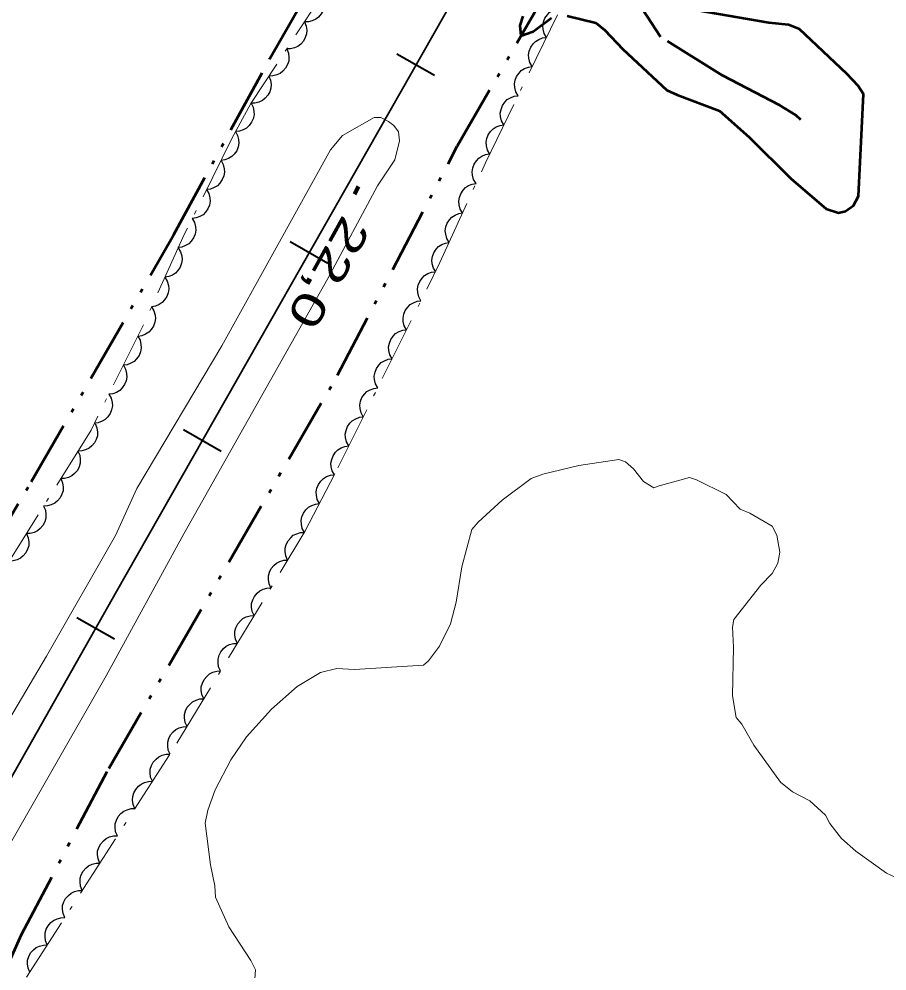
# Model space of a CAD drawing. Extents: x 386081 to 389416, y 5130568 to 5134082.
# Drawn here: x 387558.3 to 387638.7, y 5131484.2 to 5131572.3 of the extents above; entities that cross this region are included whole.
import ezdxf

# ---------------------------------------------------------------- set-up
doc = ezdxf.new("R2010")
doc.units = 0
doc.header["$LTSCALE"] = 1.2
for name, pattern in [('DASH_DOUBLE_DOT', [9.2, 5, -1.2, 0.3, -1.2, 0.3, -1.2]), ('DOT_DASHED', [7.7, 5, -1.2, 0.3, -1.2]), ('LONG_DASHED', [7.5, 6, -1.5])]:
    doc.linetypes.add(name, pattern=pattern)
for name, color, linetype, lineweight in [('1', 7, 'Continuous', 53), ('2', 7, 'Continuous', 13), ('23', 7, 'Continuous', 40), ('3', 7, 'Continuous', 140), ('4', 7, 'DASH_DOUBLE_DOT', 53), ('44', 7, 'Continuous', 25)]:
    doc.layers.add(name, color=color, linetype=linetype, lineweight=lineweight)

msp = doc.modelspace()

# ---------------------------------------------------------------- linework, layer by layer
at = {"layer": '1'}
for points in [[(387604.96, 5131572.54), (387604.69, 5131571.68), (387604.76, 5131570.72), (387605.92, 5131571.13), (387607.6, 5131572.4)], [(387609.06, 5131572.59), (387611.71, 5131571.93), (387612.56, 5131571.24), (387614.23, 5131569.49), (387618.3, 5131565.7), (387619.23, 5131565.26), (387623.17, 5131563.79), (387625.91, 5131561.34), (387629.75, 5131557.51), (387633.03, 5131554.73), (387634.17, 5131554.34), (387634.83, 5131554.5), (387635.57, 5131555.03), (387636.04, 5131555.9), (387636.48, 5131565.32), (387636.01, 5131566.09), (387634.95, 5131567.21), (387630.57, 5131571.36), (387629.56, 5131571.74), (387627.73, 5131571.94), (387621.08, 5131573.07)]]:
    msp.add_lwpolyline(points, dxfattribs=at)
at = {"layer": '2'}
for points in [[(387540.55, 5131478.3), (387543.89, 5131484.44), (387548.58, 5131492.52), (387560.89, 5131513.31), (387567.26, 5131524.47), (387569.25, 5131528.82), (387577.11, 5131542.04), (387587.16, 5131560.17), (387588.27, 5131561.49), (387591.21, 5131563.16), (387591.81, 5131563.16), (387592.54, 5131562.79), (387593.02, 5131562.42), (387593.44, 5131561.86), (387593.55, 5131561.01), (387593.11, 5131559.25), (387591.5, 5131556.84), (387586.91, 5131548.26), (387573.58, 5131524.65), (387566.39, 5131511.49), (387554.33, 5131490.45), (387547.71, 5131478.33)], [(387625.07, 5131526.92), (387625.97, 5131526.54), (387628.03, 5131525.36), (387628.48, 5131524.51), (387628.75, 5131522.95), (387628.55, 5131521.92), (387628.05, 5131520.96), (387626.98, 5131519.88), (387624.5, 5131516.71), (387624.37, 5131516), (387624.47, 5131514.15), (387624.36, 5131509.63), (387624.7, 5131507.62), (387625.22, 5131507.03), (387626.35, 5131505.09), (387628.82, 5131501.66), (387629.92, 5131500.76), (387631.51, 5131499.92), (387632.98, 5131498.58), (387633.36, 5131497.82), (387634.46, 5131496.44), (387635.79, 5131495.25), (387638.61, 5131493.23), (387640.62, 5131492.3)]]:
    msp.add_lwpolyline(points, dxfattribs=at)
at = {"layer": '2', "linetype": 'LONG_DASHED'}
for points in [[(387595.77, 5131512.49), (387596.24, 5131512.88), (387597.24, 5131514.25), (387598.26, 5131516.32), (387598.79, 5131518.3), (387599.33, 5131521.57), (387600.23, 5131525.03), (387600.83, 5131525.72), (387603.04, 5131527.76), (387605.74, 5131529.75), (387606.82, 5131530.15), (387610.15, 5131530.96), (387613.85, 5131531.53), (387614.46, 5131531.29), (387615.21, 5131530.65), (387616.13, 5131529.47), (387617.09, 5131528.88), (387617.57, 5131529.09), (387620.4, 5131529.86), (387621.04, 5131529.63), (387623.78, 5131528.29), (387625.07, 5131526.92)], [(387579.94, 5131480.88), (387580.22, 5131484.29), (387579.78, 5131485.13), (387577.76, 5131488.26), (387576.51, 5131491.01), (387576.47, 5131492.05), (387576.05, 5131494.01), (387575.56, 5131497.84), (387575.8, 5131499.05), (387576.49, 5131500.95), (387577.93, 5131503.71), (387579.4, 5131505.84), (387581.71, 5131508.41), (387584.09, 5131510.51), (387586.25, 5131511.79), (387587.76, 5131512.16), (387589.38, 5131512.09), (387595.77, 5131512.49)]]:
    msp.add_lwpolyline(points, dxfattribs=at)
at = {"layer": '23'}
for p, q in [((387593.31, 5131569.07), (387596.79, 5131567.09)), ((387583.44, 5131551.68), (387586.91, 5131549.7)), ((387573.56, 5131534.29), (387577.04, 5131532.3)), ((387563.69, 5131516.88), (387567.17, 5131514.92))]:
    msp.add_line(p, q, dxfattribs=at)
at = {"layer": '23', "lineweight": 35}
msp.add_lwpolyline([(388350.66, 5132898.63), (388202.91, 5132638.38), (388174.85, 5132589.18), (388148.16, 5132542.09), (388122.46, 5132497.01), (388036.96, 5132346.4), (388027.91, 5132330.61), (387994.29, 5132271.3), (387943.96, 5132182.8), (387915.65, 5132132.74), (387888.36, 5132084.71), (387863.09, 5132039.98), (387797.42, 5131924.62), (387647.54, 5131660.34), (387567.35, 5131519.3), (387534.84, 5131461.86), (387476.24, 5131358.73)], dxfattribs=at)
at = {"layer": '3'}
msp.add_line((387589.76, 5131556.79), (387589.37, 5131556.09), dxfattribs=at)
at = {"layer": '4'}
for points in [[(387542.58, 5131491.37), (387538.76, 5131492.88), (387540.3, 5131495.55), (387549.6, 5131512.73), (387559.47, 5131529.44), (387572.66, 5131552.34), (387581.55, 5131568.63), (387589.33, 5131582.17), (387594.48, 5131592.2), (387598.48, 5131601.01), (387601.21, 5131603.88)], [(387630.68, 5131562.95), (387630.24, 5131563.38), (387628.7, 5131564.3), (387623.43, 5131567.05), (387617.7, 5131570.63), (387613.12, 5131577.72), (387610.37, 5131581.22)], [(387566.42, 5131303.9), (387530.96, 5131346.09), (387515.69, 5131364.76), (387501.67, 5131380.58), (387499.1, 5131383.05), (387500.67, 5131386.61), (387516.18, 5131411.59), (387529.43, 5131434.73), (387541.53, 5131455.63), (387550.92, 5131473.93), (387557.21, 5131484.48), (387558.57, 5131487.55), (387566.63, 5131502.92), (387587.82, 5131539.32), (387598.88, 5131560.51), (387607.65, 5131575.65), (387611.01, 5131580.38)]]:
    msp.add_lwpolyline(points, dxfattribs=at)
at = {"layer": '44', "linetype": 'DOT_DASHED', "lineweight": 13}
for points in [[(387559.03, 5131483.59), (387572.94, 5131505.25), (387584.8, 5131524.86), (387587.84, 5131530.74), (387597.29, 5131549.74), (387601.5, 5131558.98), (387608.41, 5131573.21), (387610.77, 5131577.13), (387616.62, 5131586.21), (387623.15, 5131596.99), (387625.99, 5131602.26), (387629.7, 5131608.49), (387640.15, 5131626.74)], [(387602.48, 5131599.01), (387579.79, 5131564.47), (387578.03, 5131561.22), (387573.66, 5131552.4), (387569.76, 5131543.8), (387565, 5131534.24), (387545.23, 5131502.58), (387543.56, 5131500.59), (387539.99, 5131495.88), (387539.05, 5131493.88), (387538.04, 5131490.97), (387535.31, 5131484.12)]]:
    msp.add_lwpolyline(points, dxfattribs=at)
at = {"layer": '44'}
for points in [[(387586.4, 5131574.53), (387586.56, 5131574.15), (387586.6, 5131573.74), (387586.59, 5131573.41), (387586.48, 5131573.08), (387586.3, 5131572.76), (387586.04, 5131572.47), (387585.8, 5131572.26), (387585.47, 5131572.12), (387585.11, 5131572.03), (387584.75, 5131572.03)], [(387607.14, 5131570.59), (387606.93, 5131570.95), (387606.84, 5131571.35), (387606.8, 5131571.67), (387606.87, 5131572.02), (387607, 5131572.36), (387607.23, 5131572.68), (387607.44, 5131572.92), (387607.75, 5131573.1), (387608.09, 5131573.24), (387608.45, 5131573.29)], [(387584.75, 5131572.03), (387584.91, 5131571.64), (387584.96, 5131571.24), (387584.94, 5131570.91), (387584.83, 5131570.57), (387584.66, 5131570.25), (387584.4, 5131569.97), (387584.15, 5131569.75), (387583.83, 5131569.61), (387583.47, 5131569.52), (387583.11, 5131569.52)], [(387605.83, 5131567.89), (387605.62, 5131568.25), (387605.53, 5131568.65), (387605.49, 5131568.98), (387605.56, 5131569.32), (387605.69, 5131569.67), (387605.92, 5131569.98), (387606.13, 5131570.22), (387606.44, 5131570.4), (387606.78, 5131570.54), (387607.14, 5131570.59)], [(387583.11, 5131569.52), (387583.27, 5131569.13), (387583.31, 5131568.73), (387583.3, 5131568.4), (387583.19, 5131568.07), (387583.01, 5131567.74), (387582.75, 5131567.46), (387582.5, 5131567.25), (387582.18, 5131567.11), (387581.82, 5131567.02), (387581.46, 5131567.01)], [(387604.52, 5131565.19), (387604.31, 5131565.55), (387604.21, 5131565.95), (387604.18, 5131566.28), (387604.25, 5131566.62), (387604.38, 5131566.97), (387604.61, 5131567.28), (387604.82, 5131567.52), (387605.12, 5131567.7), (387605.47, 5131567.84), (387605.83, 5131567.89)], [(387581.46, 5131567.01), (387581.62, 5131566.63), (387581.66, 5131566.22), (387581.65, 5131565.89), (387581.54, 5131565.56), (387581.36, 5131565.23), (387581.1, 5131564.95), (387580.86, 5131564.74), (387580.53, 5131564.6), (387580.17, 5131564.51), (387579.81, 5131564.5)], [(387603.21, 5131562.49), (387603, 5131562.85), (387602.9, 5131563.25), (387602.87, 5131563.58), (387602.94, 5131563.92), (387603.07, 5131564.27), (387603.29, 5131564.58), (387603.51, 5131564.83), (387603.81, 5131565), (387604.16, 5131565.14), (387604.52, 5131565.19)], [(387579.81, 5131564.51), (387580, 5131564.14), (387580.08, 5131563.74), (387580.09, 5131563.41), (387580.01, 5131563.06), (387579.86, 5131562.73), (387579.63, 5131562.42), (387579.4, 5131562.19), (387579.09, 5131562.02), (387578.74, 5131561.9), (387578.38, 5131561.87)], [(387578.36, 5131561.88), (387578.56, 5131561.52), (387578.65, 5131561.12), (387578.68, 5131560.79), (387578.61, 5131560.45), (387578.48, 5131560.1), (387578.25, 5131559.79), (387578.03, 5131559.55), (387577.73, 5131559.37), (387577.38, 5131559.24), (387577.03, 5131559.19)], [(387601.9, 5131559.79), (387601.69, 5131560.16), (387601.59, 5131560.55), (387601.56, 5131560.88), (387601.63, 5131561.23), (387601.76, 5131561.57), (387601.98, 5131561.88), (387602.2, 5131562.13), (387602.5, 5131562.31), (387602.85, 5131562.44), (387603.21, 5131562.49)], [(387577.03, 5131559.19), (387577.23, 5131558.83), (387577.32, 5131558.43), (387577.35, 5131558.1), (387577.28, 5131557.76), (387577.14, 5131557.42), (387576.92, 5131557.1), (387576.7, 5131556.86), (387576.4, 5131556.69), (387576.05, 5131556.55), (387575.69, 5131556.5)], [(387600.63, 5131557.07), (387600.41, 5131557.43), (387600.31, 5131557.82), (387600.27, 5131558.15), (387600.33, 5131558.5), (387600.45, 5131558.85), (387600.67, 5131559.16), (387600.88, 5131559.41), (387601.18, 5131559.6), (387601.52, 5131559.74), (387601.88, 5131559.8)], [(387575.69, 5131556.5), (387575.9, 5131556.14), (387575.99, 5131555.74), (387576.02, 5131555.42), (387575.95, 5131555.07), (387575.81, 5131554.73), (387575.59, 5131554.42), (387575.37, 5131554.17), (387575.07, 5131554), (387574.72, 5131553.87), (387574.36, 5131553.82)], [(387599.39, 5131554.34), (387599.17, 5131554.7), (387599.07, 5131555.09), (387599.03, 5131555.42), (387599.09, 5131555.77), (387599.21, 5131556.12), (387599.43, 5131556.43), (387599.64, 5131556.68), (387599.93, 5131556.87), (387600.28, 5131557.01), (387600.63, 5131557.07)], [(387574.36, 5131553.82), (387574.57, 5131553.45), (387574.66, 5131553.06), (387574.69, 5131552.73), (387574.62, 5131552.38), (387574.48, 5131552.04), (387574.26, 5131551.73), (387574.04, 5131551.49), (387573.73, 5131551.31), (387573.39, 5131551.18), (387573.03, 5131551.13)], [(387598.14, 5131551.61), (387597.93, 5131551.97), (387597.82, 5131552.36), (387597.78, 5131552.69), (387597.84, 5131553.04), (387597.97, 5131553.39), (387598.18, 5131553.7), (387598.39, 5131553.95), (387598.69, 5131554.14), (387599.03, 5131554.28), (387599.39, 5131554.34)], [(387573.07, 5131551.11), (387573.29, 5131550.75), (387573.39, 5131550.36), (387573.44, 5131550.03), (387573.38, 5131549.68), (387573.25, 5131549.33), (387573.04, 5131549.02), (387572.83, 5131548.77), (387572.53, 5131548.58), (387572.19, 5131548.44), (387571.83, 5131548.38)], [(387596.9, 5131548.88), (387596.68, 5131549.24), (387596.58, 5131549.63), (387596.54, 5131549.96), (387596.6, 5131550.31), (387596.72, 5131550.66), (387596.94, 5131550.97), (387597.15, 5131551.22), (387597.45, 5131551.41), (387597.79, 5131551.55), (387598.14, 5131551.61)], [(387595.53, 5131546.21), (387595.33, 5131546.57), (387595.24, 5131546.97), (387595.21, 5131547.3), (387595.28, 5131547.64), (387595.42, 5131547.99), (387595.64, 5131548.3), (387595.86, 5131548.54), (387596.17, 5131548.72), (387596.51, 5131548.85), (387596.87, 5131548.9)], [(387571.83, 5131548.38), (387572.05, 5131548.02), (387572.16, 5131547.63), (387572.2, 5131547.3), (387572.14, 5131546.95), (387572.01, 5131546.6), (387571.8, 5131546.28), (387571.59, 5131546.04), (387571.29, 5131545.85), (387570.95, 5131545.7), (387570.6, 5131545.64)], [(387594.2, 5131543.52), (387593.99, 5131543.89), (387593.9, 5131544.29), (387593.88, 5131544.61), (387593.95, 5131544.96), (387594.08, 5131545.3), (387594.31, 5131545.61), (387594.53, 5131545.85), (387594.83, 5131546.03), (387595.18, 5131546.16), (387595.53, 5131546.21)], [(387570.6, 5131545.64), (387570.81, 5131545.29), (387570.92, 5131544.89), (387570.96, 5131544.57), (387570.9, 5131544.22), (387570.78, 5131543.87), (387570.56, 5131543.55), (387570.35, 5131543.3), (387570.05, 5131543.12), (387569.71, 5131542.97), (387569.36, 5131542.91)], [(387592.86, 5131540.84), (387592.66, 5131541.2), (387592.57, 5131541.6), (387592.54, 5131541.93), (387592.61, 5131542.27), (387592.75, 5131542.62), (387592.97, 5131542.93), (387593.19, 5131543.17), (387593.5, 5131543.35), (387593.84, 5131543.48), (387594.2, 5131543.52)], [(387569.32, 5131542.93), (387569.53, 5131542.56), (387569.62, 5131542.17), (387569.65, 5131541.84), (387569.58, 5131541.49), (387569.44, 5131541.15), (387569.21, 5131540.84), (387569, 5131540.6), (387568.69, 5131540.42), (387568.34, 5131540.29), (387567.99, 5131540.24)], [(387591.53, 5131538.15), (387591.32, 5131538.52), (387591.23, 5131538.91), (387591.2, 5131539.24), (387591.28, 5131539.59), (387591.41, 5131539.93), (387591.64, 5131540.24), (387591.85, 5131540.48), (387592.16, 5131540.66), (387592.51, 5131540.79), (387592.86, 5131540.84)], [(387567.99, 5131540.24), (387568.19, 5131539.88), (387568.28, 5131539.48), (387568.31, 5131539.15), (387568.24, 5131538.81), (387568.1, 5131538.46), (387567.88, 5131538.15), (387567.66, 5131537.91), (387567.35, 5131537.73), (387567.01, 5131537.6), (387566.65, 5131537.56)], [(387590.19, 5131535.47), (387589.99, 5131535.83), (387589.9, 5131536.23), (387589.87, 5131536.56), (387589.94, 5131536.9), (387590.07, 5131537.24), (387590.3, 5131537.55), (387590.52, 5131537.8), (387590.82, 5131537.97), (387591.17, 5131538.1), (387591.53, 5131538.15)], [(387566.65, 5131537.56), (387566.86, 5131537.19), (387566.94, 5131536.79), (387566.97, 5131536.47), (387566.9, 5131536.12), (387566.77, 5131535.78), (387566.54, 5131535.47), (387566.32, 5131535.23), (387566.02, 5131535.05), (387565.67, 5131534.92), (387565.31, 5131534.87)], [(387588.85, 5131532.78), (387588.65, 5131533.14), (387588.56, 5131533.54), (387588.53, 5131533.87), (387588.6, 5131534.21), (387588.74, 5131534.56), (387588.96, 5131534.87), (387589.18, 5131535.11), (387589.49, 5131535.29), (387589.83, 5131535.42), (387590.19, 5131535.47)], [(387565.37, 5131534.84), (387565.54, 5131534.45), (387565.59, 5131534.05), (387565.59, 5131533.72), (387565.48, 5131533.38), (387565.32, 5131533.06), (387565.06, 5131532.77), (387564.82, 5131532.55), (387564.5, 5131532.4), (387564.14, 5131532.31), (387563.78, 5131532.29)], [(387587.52, 5131530.09), (387587.31, 5131530.46), (387587.22, 5131530.85), (387587.2, 5131531.18), (387587.27, 5131531.53), (387587.4, 5131531.87), (387587.63, 5131532.18), (387587.85, 5131532.42), (387588.15, 5131532.6), (387588.5, 5131532.73), (387588.85, 5131532.78)], [(387563.78, 5131532.29), (387563.95, 5131531.91), (387564, 5131531.51), (387564, 5131531.18), (387563.9, 5131530.84), (387563.73, 5131530.51), (387563.47, 5131530.22), (387563.23, 5131530), (387562.91, 5131529.86), (387562.55, 5131529.76), (387562.19, 5131529.75)], [(387586.13, 5131527.43), (387585.93, 5131527.8), (387585.85, 5131528.2), (387585.83, 5131528.53), (387585.9, 5131528.87), (387586.04, 5131529.21), (387586.27, 5131529.52), (387586.5, 5131529.76), (387586.8, 5131529.93), (387587.15, 5131530.06), (387587.51, 5131530.1)], [(387562.19, 5131529.75), (387562.36, 5131529.37), (387562.41, 5131528.96), (387562.41, 5131528.63), (387562.31, 5131528.3), (387562.14, 5131527.97), (387561.88, 5131527.68), (387561.64, 5131527.46), (387561.32, 5131527.31), (387560.97, 5131527.22), (387560.61, 5131527.2)], [(387584.75, 5131524.77), (387584.55, 5131525.14), (387584.47, 5131525.53), (387584.45, 5131525.86), (387584.52, 5131526.21), (387584.66, 5131526.55), (387584.89, 5131526.86), (387585.12, 5131527.09), (387585.42, 5131527.27), (387585.77, 5131527.39), (387586.13, 5131527.43)], [(387560.61, 5131527.2), (387560.78, 5131526.82), (387560.82, 5131526.42), (387560.82, 5131526.09), (387560.72, 5131525.75), (387560.55, 5131525.42), (387560.3, 5131525.14), (387560.05, 5131524.92), (387559.73, 5131524.77), (387559.38, 5131524.67), (387559.02, 5131524.66)], [(387559.02, 5131524.66), (387559.19, 5131524.28), (387559.24, 5131523.87), (387559.23, 5131523.54), (387559.13, 5131523.21), (387558.96, 5131522.88), (387558.71, 5131522.59), (387558.47, 5131522.37), (387558.15, 5131522.22), (387557.79, 5131522.13), (387557.43, 5131522.11)], [(387583.19, 5131522.21), (387583.02, 5131522.59), (387582.96, 5131522.99), (387582.96, 5131523.32), (387583.06, 5131523.66), (387583.23, 5131523.99), (387583.48, 5131524.28), (387583.71, 5131524.5), (387584.03, 5131524.65), (387584.39, 5131524.75), (387584.75, 5131524.77)], [(387581.64, 5131519.64), (387581.47, 5131520.02), (387581.41, 5131520.42), (387581.41, 5131520.75), (387581.51, 5131521.09), (387581.67, 5131521.42), (387581.92, 5131521.71), (387582.16, 5131521.93), (387582.48, 5131522.08), (387582.84, 5131522.19), (387583.19, 5131522.21)], [(387580.09, 5131517.07), (387579.91, 5131517.45), (387579.86, 5131517.85), (387579.86, 5131518.18), (387579.96, 5131518.52), (387580.12, 5131518.85), (387580.37, 5131519.14), (387580.61, 5131519.37), (387580.93, 5131519.52), (387581.28, 5131519.62), (387581.64, 5131519.64)], [(387578.54, 5131514.5), (387578.36, 5131514.88), (387578.31, 5131515.29), (387578.31, 5131515.62), (387578.4, 5131515.95), (387578.57, 5131516.29), (387578.82, 5131516.58), (387579.06, 5131516.8), (387579.37, 5131516.95), (387579.73, 5131517.05), (387580.09, 5131517.07)], [(387576.98, 5131511.94), (387576.81, 5131512.32), (387576.75, 5131512.72), (387576.75, 5131513.05), (387576.85, 5131513.39), (387577.01, 5131513.72), (387577.27, 5131514.01), (387577.5, 5131514.23), (387577.82, 5131514.38), (387578.18, 5131514.49), (387578.54, 5131514.5)], [(387575.43, 5131509.37), (387575.26, 5131509.75), (387575.2, 5131510.15), (387575.2, 5131510.48), (387575.3, 5131510.82), (387575.46, 5131511.15), (387575.71, 5131511.44), (387575.95, 5131511.67), (387576.27, 5131511.82), (387576.63, 5131511.92), (387576.98, 5131511.94)], [(387573.88, 5131506.8), (387573.7, 5131507.18), (387573.65, 5131507.59), (387573.65, 5131507.92), (387573.75, 5131508.25), (387573.91, 5131508.59), (387574.16, 5131508.88), (387574.4, 5131509.1), (387574.72, 5131509.25), (387575.07, 5131509.35), (387575.43, 5131509.37)], [(387572.33, 5131504.24), (387572.15, 5131504.62), (387572.1, 5131505.02), (387572.1, 5131505.35), (387572.19, 5131505.69), (387572.36, 5131506.02), (387572.61, 5131506.31), (387572.85, 5131506.53), (387573.16, 5131506.68), (387573.52, 5131506.78), (387573.88, 5131506.8)], [(387570.68, 5131501.73), (387570.51, 5131502.11), (387570.47, 5131502.52), (387570.48, 5131502.85), (387570.59, 5131503.18), (387570.76, 5131503.51), (387571.02, 5131503.79), (387571.26, 5131504.01), (387571.58, 5131504.15), (387571.94, 5131504.24), (387572.3, 5131504.25)], [(387569.06, 5131499.2), (387568.89, 5131499.59), (387568.85, 5131499.99), (387568.86, 5131500.32), (387568.96, 5131500.66), (387569.14, 5131500.98), (387569.39, 5131501.27), (387569.64, 5131501.48), (387569.96, 5131501.63), (387570.32, 5131501.72), (387570.68, 5131501.73)], [(387567.44, 5131496.68), (387567.27, 5131497.06), (387567.23, 5131497.47), (387567.24, 5131497.8), (387567.34, 5131498.13), (387567.51, 5131498.46), (387567.77, 5131498.74), (387568.02, 5131498.96), (387568.34, 5131499.1), (387568.7, 5131499.2), (387569.06, 5131499.2)], [(387565.82, 5131494.16), (387565.65, 5131494.54), (387565.61, 5131494.94), (387565.61, 5131495.27), (387565.72, 5131495.61), (387565.89, 5131495.94), (387566.15, 5131496.22), (387566.4, 5131496.44), (387566.72, 5131496.58), (387567.08, 5131496.67), (387567.44, 5131496.68)], [(387564.19, 5131491.63), (387564.03, 5131492.02), (387563.99, 5131492.42), (387563.99, 5131492.75), (387564.1, 5131493.08), (387564.27, 5131493.41), (387564.53, 5131493.7), (387564.77, 5131493.91), (387565.1, 5131494.05), (387565.46, 5131494.15), (387565.82, 5131494.16)], [(387562.57, 5131489.11), (387562.41, 5131489.49), (387562.36, 5131489.9), (387562.37, 5131490.23), (387562.48, 5131490.56), (387562.65, 5131490.89), (387562.91, 5131491.17), (387563.15, 5131491.39), (387563.48, 5131491.53), (387563.83, 5131491.62), (387564.19, 5131491.63)], [(387560.95, 5131486.58), (387560.79, 5131486.97), (387560.74, 5131487.37), (387560.75, 5131487.7), (387560.86, 5131488.04), (387561.03, 5131488.36), (387561.29, 5131488.65), (387561.53, 5131488.86), (387561.85, 5131489.01), (387562.21, 5131489.1), (387562.57, 5131489.11)], [(387559.33, 5131484.06), (387559.17, 5131484.44), (387559.12, 5131484.85), (387559.13, 5131485.18), (387559.24, 5131485.51), (387559.41, 5131485.84), (387559.67, 5131486.12), (387559.91, 5131486.34), (387560.23, 5131486.48), (387560.59, 5131486.57), (387560.95, 5131486.58)]]:
    msp.add_lwpolyline(points, dxfattribs=at)

# ---------------------------------------------------------------- texts
at = {"layer": '3', "width": 1.4}
msp.add_text('22,0   ', height=3, rotation=241.032, dxfattribs=at).set_placement((387588.33, 5131554.29))

doc.saveas('drawing.dxf')
